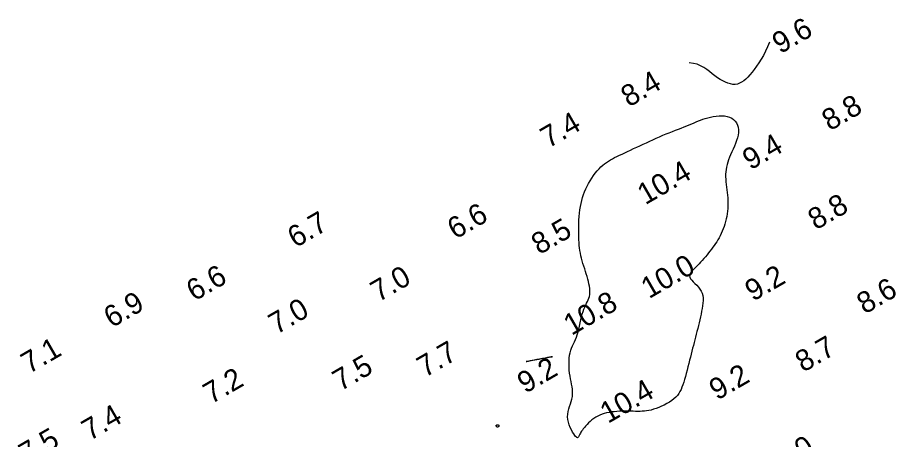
# Model space of a CAD drawing. Extents: x 3024098 to 3056816, y 418252 to 509144.
# Drawn here: x 3035124 to 3035329.1, y 419450.4 to 419549.8 of the extents above; entities that cross this region are included whole.
import ezdxf

# ---------------------------------------------------------------- set-up
doc = ezdxf.new("R2010")
doc.units = 0
doc.layers.add('V-CHAN-CONT-EL10', color=7, linetype='Continuous')
doc.layers.add('V-TOPO-SOUN-0911', color=7, linetype='Continuous')

msp = doc.modelspace()

# ---------------------------------------------------------------- linework, layer by layer
at = {"layer": 'V-CHAN-CONT-EL10'}
msp.add_lwpolyline([(3035301.24, 419543.94), (3035300.78, 419542.85), (3035300.29, 419541.83), (3035299.79, 419540.86), (3035299.26, 419539.95), (3035298.72, 419539.09), (3035298.18, 419538.3), (3035297.65, 419537.56), (3035297.12, 419536.89), (3035296.62, 419536.28), (3035296.12, 419535.73), (3035295.63, 419535.25), (3035295.15, 419534.85), (3035294.66, 419534.52), (3035294.16, 419534.27), (3035293.66, 419534.1), (3035293.13, 419534.02), (3035292.58, 419534.03), (3035292.02, 419534.12), (3035291.44, 419534.29), (3035290.84, 419534.52), (3035290.23, 419534.82), (3035289.62, 419535.18), (3035289, 419535.59), (3035288.37, 419536.05), (3035287.75, 419536.54), (3035287.11, 419537.05), (3035286.45, 419537.54), (3035285.75, 419538.01), (3035285, 419538.42), (3035284.19, 419538.75), (3035283.3, 419538.97), (3035282.32, 419539.07)], dxfattribs=at)
for points in [[(3035253.7, 419456.39), (3035253.8, 419457.01), (3035253.95, 419457.61), (3035254.13, 419458.2), (3035254.33, 419458.79), (3035254.52, 419459.36), (3035254.68, 419459.93), (3035254.79, 419460.5), (3035254.84, 419461.07), (3035254.84, 419461.64), (3035254.79, 419462.22), (3035254.7, 419462.81), (3035254.59, 419463.41), (3035254.47, 419464.03), (3035254.35, 419464.67), (3035254.23, 419465.33), (3035254.13, 419466.03), (3035254.06, 419466.74), (3035254.01, 419467.46), (3035253.99, 419468.18), (3035254, 419468.89), (3035254.04, 419469.58), (3035254.12, 419470.23), (3035254.23, 419470.85), (3035254.39, 419471.41), (3035254.58, 419471.94), (3035254.79, 419472.44), (3035255.02, 419472.93), (3035255.26, 419473.43), (3035255.5, 419473.95), (3035255.73, 419474.49), (3035255.95, 419475.08), (3035256.14, 419475.72), (3035256.32, 419476.4), (3035256.48, 419477.12), (3035256.64, 419477.84), (3035256.79, 419478.56), (3035256.95, 419479.26), (3035257.12, 419479.92), (3035257.3, 419480.54), (3035257.5, 419481.09), (3035257.71, 419481.59), (3035257.92, 419482.04), (3035258.13, 419482.47), (3035258.33, 419482.87), (3035258.51, 419483.27), (3035258.67, 419483.66), (3035258.78, 419484.08), (3035258.86, 419484.51), (3035258.9, 419484.97), (3035258.9, 419485.46), (3035258.86, 419485.96), (3035258.79, 419486.49), (3035258.69, 419487.03), (3035258.57, 419487.6), (3035258.42, 419488.18), (3035258.25, 419488.77), (3035258.07, 419489.38), (3035257.87, 419489.99), (3035257.68, 419490.61), (3035257.48, 419491.23), (3035257.28, 419491.86), (3035257.1, 419492.47), (3035256.94, 419493.09), (3035256.8, 419493.69), (3035256.67, 419494.29), (3035256.57, 419494.89), (3035256.48, 419495.5), (3035256.42, 419496.12), (3035256.36, 419496.76), (3035256.32, 419497.43), (3035256.29, 419498.14), (3035256.28, 419498.88), (3035256.27, 419499.65), (3035256.28, 419500.44), (3035256.3, 419501.25), (3035256.34, 419502.06), (3035256.4, 419502.88), (3035256.47, 419503.68), (3035256.57, 419504.47), (3035256.69, 419505.23), (3035256.83, 419505.97), (3035257, 419506.69), (3035257.19, 419507.39), (3035257.41, 419508.07), (3035257.66, 419508.75), (3035257.94, 419509.41), (3035258.25, 419510.06), (3035258.59, 419510.7), (3035258.96, 419511.33), (3035259.36, 419511.95), (3035259.77, 419512.54), (3035260.19, 419513.1), (3035260.63, 419513.63), (3035261.06, 419514.12), (3035261.5, 419514.57), (3035261.94, 419514.97), (3035262.37, 419515.33), (3035262.81, 419515.66), (3035263.26, 419515.96), (3035263.73, 419516.24), (3035264.21, 419516.51), (3035264.73, 419516.77), (3035265.28, 419517.04), (3035265.86, 419517.33), (3035266.48, 419517.62), (3035267.13, 419517.92), (3035267.8, 419518.24), (3035268.5, 419518.56), (3035269.22, 419518.89), (3035269.96, 419519.23), (3035270.71, 419519.58), (3035271.47, 419519.93), (3035272.23, 419520.29), (3035273.01, 419520.65), (3035273.78, 419521), (3035274.55, 419521.35), (3035275.32, 419521.7), (3035276.09, 419522.03), (3035276.85, 419522.35), (3035277.6, 419522.65), (3035278.34, 419522.94), (3035279.06, 419523.22), (3035279.77, 419523.48), (3035280.45, 419523.74), (3035281.11, 419523.99), (3035281.74, 419524.23), (3035282.34, 419524.47), (3035282.9, 419524.71), (3035283.45, 419524.95), (3035283.97, 419525.18), (3035284.49, 419525.4), (3035285.01, 419525.61), (3035285.55, 419525.82), (3035286.11, 419526), (3035286.7, 419526.18), (3035287.33, 419526.33), (3035287.99, 419526.46), (3035288.66, 419526.56), (3035289.34, 419526.62), (3035290.01, 419526.63), (3035290.65, 419526.58), (3035291.27, 419526.48), (3035291.83, 419526.31), (3035292.34, 419526.06), (3035292.78, 419525.75), (3035293.16, 419525.37), (3035293.47, 419524.93), (3035293.71, 419524.44), (3035293.87, 419523.91), (3035293.95, 419523.34), (3035293.94, 419522.73), (3035293.86, 419522.1), (3035293.7, 419521.45), (3035293.49, 419520.78), (3035293.23, 419520.11), (3035292.95, 419519.44), (3035292.65, 419518.77), (3035292.35, 419518.11), (3035292.07, 419517.47), (3035291.81, 419516.86), (3035291.58, 419516.27), (3035291.39, 419515.69), (3035291.22, 419515.12), (3035291.09, 419514.56), (3035290.99, 419513.99), (3035290.92, 419513.43), (3035290.89, 419512.86), (3035290.9, 419512.27), (3035290.93, 419511.67), (3035290.98, 419511.06), (3035291.05, 419510.45), (3035291.13, 419509.83), (3035291.21, 419509.2), (3035291.29, 419508.57), (3035291.35, 419507.94), (3035291.4, 419507.31), (3035291.43, 419506.68), (3035291.43, 419506.05), (3035291.42, 419505.42), (3035291.39, 419504.8), (3035291.33, 419504.18), (3035291.25, 419503.56), (3035291.15, 419502.95), (3035291.02, 419502.34), (3035290.88, 419501.73), (3035290.71, 419501.14), (3035290.52, 419500.55), (3035290.31, 419499.98), (3035290.09, 419499.43), (3035289.85, 419498.9), (3035289.6, 419498.38), (3035289.34, 419497.89), (3035289.07, 419497.42), (3035288.79, 419496.97), (3035288.49, 419496.52), (3035288.19, 419496.09), (3035287.87, 419495.66), (3035287.54, 419495.23), (3035287.21, 419494.79), (3035286.86, 419494.35), (3035286.51, 419493.9), (3035286.14, 419493.45), (3035285.77, 419493.01), (3035285.4, 419492.57), (3035285.01, 419492.14), (3035284.63, 419491.73), (3035284.24, 419491.34), (3035283.85, 419490.96), (3035283.48, 419490.61), (3035283.13, 419490.26), (3035282.84, 419489.93), (3035282.6, 419489.61), (3035282.45, 419489.28), (3035282.39, 419488.95), (3035282.45, 419488.62), (3035282.62, 419488.27), (3035282.9, 419487.91), (3035283.25, 419487.54), (3035283.65, 419487.14), (3035284.07, 419486.73), (3035284.48, 419486.29), (3035284.85, 419485.83), (3035285.15, 419485.35), (3035285.38, 419484.83), (3035285.52, 419484.29), (3035285.59, 419483.73), (3035285.6, 419483.14), (3035285.56, 419482.53), (3035285.47, 419481.91), (3035285.36, 419481.27), (3035285.23, 419480.61), (3035285.1, 419479.95), (3035284.95, 419479.27), (3035284.79, 419478.59), (3035284.64, 419477.91), (3035284.47, 419477.22), (3035284.31, 419476.54), (3035284.14, 419475.86), (3035283.97, 419475.2), (3035283.8, 419474.54), (3035283.63, 419473.88), (3035283.46, 419473.23), (3035283.29, 419472.57), (3035283.12, 419471.9), (3035282.94, 419471.22), (3035282.76, 419470.52), (3035282.58, 419469.8), (3035282.39, 419469.05), (3035282.2, 419468.29), (3035282, 419467.51), (3035281.81, 419466.74), (3035281.61, 419465.98), (3035281.41, 419465.24), (3035281.21, 419464.54), (3035281.01, 419463.87), (3035280.81, 419463.26), (3035280.6, 419462.69), (3035280.38, 419462.16), (3035280.13, 419461.67), (3035279.85, 419461.2), (3035279.52, 419460.77), (3035279.14, 419460.35), (3035278.71, 419459.95), (3035278.21, 419459.57), (3035277.65, 419459.2), (3035277.05, 419458.85), (3035276.43, 419458.52), (3035275.79, 419458.22), (3035275.15, 419457.94), (3035274.52, 419457.71), (3035273.91, 419457.51), (3035273.34, 419457.35), (3035272.8, 419457.23), (3035272.28, 419457.14), (3035271.77, 419457.08), (3035271.26, 419457.05), (3035270.75, 419457.03), (3035270.22, 419457.03), (3035269.67, 419457.03), (3035269.08, 419457.04), (3035268.47, 419457.06), (3035267.85, 419457.07), (3035267.2, 419457.07), (3035266.55, 419457.07), (3035265.9, 419457.05), (3035265.26, 419457.02), (3035264.63, 419456.96), (3035264.02, 419456.89), (3035263.42, 419456.79), (3035262.85, 419456.67), (3035262.3, 419456.52), (3035261.77, 419456.34), (3035261.25, 419456.14), (3035260.75, 419455.9), (3035260.28, 419455.63), (3035259.82, 419455.33), (3035259.39, 419455), (3035258.98, 419454.65), (3035258.59, 419454.3), (3035258.23, 419453.94), (3035257.91, 419453.58), (3035257.62, 419453.24), (3035257.36, 419452.92), (3035257.14, 419452.62), (3035256.96, 419452.35), (3035256.8, 419452.11), (3035256.67, 419451.89), (3035256.56, 419451.69), (3035256.46, 419451.51), (3035256.38, 419451.34), (3035256.31, 419451.19), (3035256.23, 419451.05), (3035256.16, 419450.94), (3035256.07, 419450.86), (3035255.98, 419450.83), (3035255.86, 419450.85), (3035255.72, 419450.94), (3035255.55, 419451.11), (3035255.34, 419451.37), (3035255.1, 419451.72), (3035254.83, 419452.16), (3035254.56, 419452.67), (3035254.3, 419453.23), (3035254.06, 419453.84), (3035253.87, 419454.47), (3035253.73, 419455.12), (3035253.67, 419455.76)], [(3035248.9, 419469.7), (3035249.3, 419469.78), (3035249.64, 419469.84), (3035249.9, 419469.88), (3035250.06, 419469.91), (3035250.1, 419469.92), (3035250.02, 419469.9), (3035249.8, 419469.86), (3035249.43, 419469.79), (3035248.94, 419469.69), (3035248.36, 419469.58), (3035247.72, 419469.46), (3035247.06, 419469.34), (3035246.41, 419469.21), (3035245.8, 419469.1), (3035245.28, 419469), (3035244.86, 419468.92), (3035244.54, 419468.86), (3035244.3, 419468.81), (3035244.13, 419468.78), (3035244.03, 419468.76), (3035243.96, 419468.75), (3035243.93, 419468.75), (3035243.91, 419468.75), (3035243.9, 419468.75), (3035243.91, 419468.76), (3035243.93, 419468.77), (3035243.99, 419468.79), (3035244.08, 419468.81), (3035244.23, 419468.84), (3035244.43, 419468.88), (3035244.7, 419468.94), (3035245.05, 419469), (3035245.46, 419469.08), (3035245.92, 419469.16), (3035246.41, 419469.25), (3035246.92, 419469.35), (3035247.44, 419469.44), (3035247.95, 419469.53), (3035248.44, 419469.62)], [(3035236.86, 419453.55), (3035236.85, 419453.59), (3035236.84, 419453.62), (3035236.83, 419453.66), (3035236.83, 419453.69), (3035236.83, 419453.72), (3035236.85, 419453.75), (3035236.86, 419453.78), (3035236.89, 419453.8), (3035236.92, 419453.81), (3035236.95, 419453.83), (3035236.98, 419453.84), (3035237.02, 419453.85), (3035237.06, 419453.85), (3035237.09, 419453.86), (3035237.13, 419453.86), (3035237.16, 419453.86), (3035237.19, 419453.86), (3035237.22, 419453.86), (3035237.25, 419453.86), (3035237.28, 419453.86), (3035237.3, 419453.85), (3035237.33, 419453.84), (3035237.35, 419453.83), (3035237.38, 419453.82), (3035237.41, 419453.8), (3035237.43, 419453.78), (3035237.45, 419453.76), (3035237.47, 419453.74), (3035237.48, 419453.71), (3035237.49, 419453.67), (3035237.48, 419453.63), (3035237.47, 419453.59), (3035237.45, 419453.54), (3035237.42, 419453.49), (3035237.38, 419453.45), (3035237.34, 419453.41), (3035237.3, 419453.37), (3035237.25, 419453.35), (3035237.21, 419453.33), (3035237.16, 419453.33), (3035237.11, 419453.33), (3035237.07, 419453.35), (3035237.02, 419453.37), (3035236.98, 419453.4), (3035236.95, 419453.44), (3035236.92, 419453.47), (3035236.89, 419453.51)]]:
    msp.add_lwpolyline(points, close=True, dxfattribs=at)

# ---------------------------------------------------------------- texts
at = {"layer": 'V-TOPO-SOUN-0911'}
for s, p in [('9.6', (3035303.75, 419541.09)), ('8.4', (3035268.09, 419528.56)), ('8.8', (3035315.44, 419522.95)), ('7.4', (3035249.13, 419518.88)), ('9.4', (3035296.74, 419513.73)), ('10.4 ', (3035271.97, 419505.55)), ('8.8', (3035312.16, 419499.62)), ('6.6', (3035227.21, 419497.43)), ('6.7', (3035189.55, 419495.42)), ('8.5', (3035246.99, 419493.81)), ('10.0 ', (3035272.84, 419483.44)), ('6.6', (3035165.7, 419482.86)), ('7.0', (3035209.09, 419482.66)), ('9.2', (3035297.33, 419482.82)), ('8.6', (3035323.67, 419479.81)), ('6.9', (3035146.24, 419476.58)), ('10.8 ', (3035254.58, 419474.78)), ('7.0', (3035185.07, 419475.04)), ('8.7', (3035309.17, 419466.12)), ('7.1', (3035126.74, 419465.78)), ('7.7', (3035220.03, 419464.91)), ('7.5', (3035200.14, 419461.69)), ('9.2', (3035243.68, 419461.13)), ('7.2', (3035169.67, 419458.64)), ('9.2', (3035288.89, 419459.53)), ('10.4 ', (3035263.17, 419454.07)), ('7.4', (3035141.04, 419450)), ('7.5', (3035126.22, 419444.47)), ('9.0', (3035304.13, 419442.69))]:
    msp.add_text(s, height=5, rotation=30, dxfattribs=at).set_placement(p)

doc.saveas('drawing.dxf')
